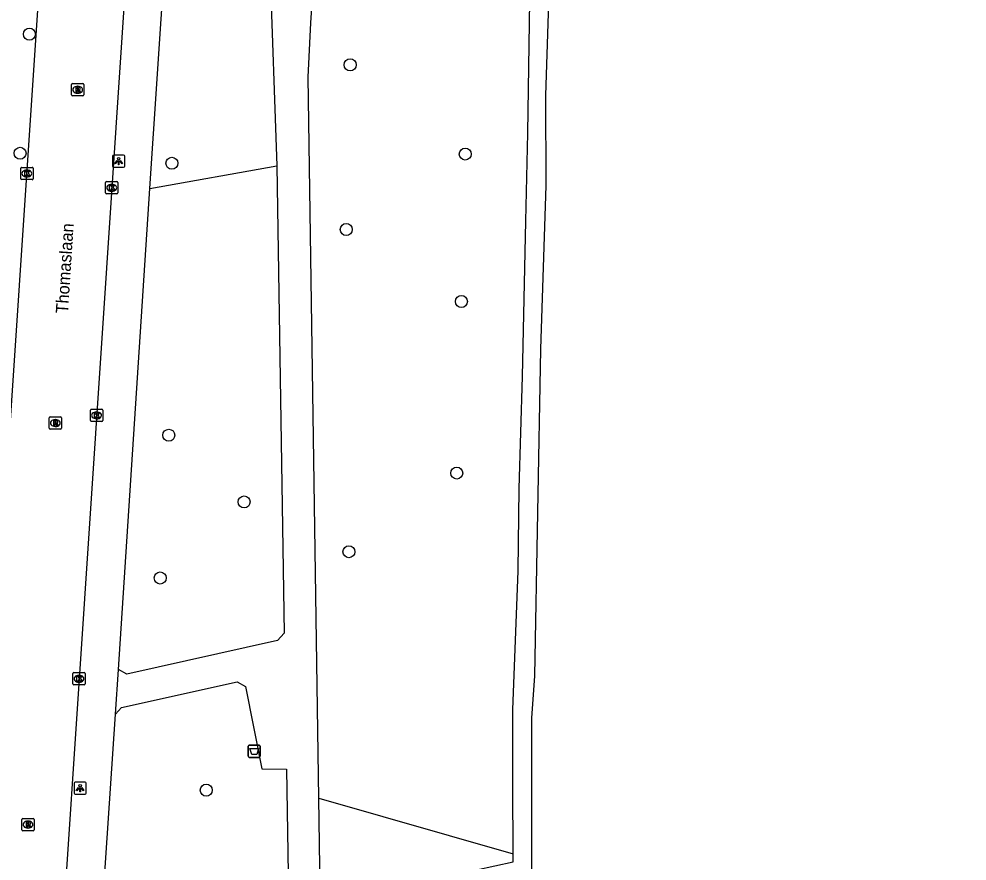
# Model space of a CAD drawing. Extents: x 161848 to 162726, y 385382 to 386521.
# Drawn here: x 162135.2 to 162212.3, y 385800.6 to 385869.2 of the extents above; entities that cross this region are included whole.
import ezdxf

# ---------------------------------------------------------------- set-up
doc = ezdxf.new("R2010")
doc.units = 0
for name, color, linetype in [('IMGEO_Afvalbak', 7, 'Continuous'), ('IMGEO_Boom', 7, 'Continuous'), ('IMGEO_Groenvoorziening', 7, 'Continuous'), ('IMGEO_Kolk', 7, 'Continuous'), ('IMGEO_Lichtpunt', 7, 'Continuous'), ('IMGEO_Openbare_ruimte_label', 7, 'Continuous'), ('IMGEO_Rijbaan_lokaal_open', 7, 'Continuous'), ('IMGEO_Rioolput', 7, 'Continuous'), ('IMGEO_Voetpad_halfverhard', 7, 'Continuous'), ('IMGEO_Voetpad_open', 7, 'Continuous'), ('IMGEO_Waterloop', 7, 'Continuous')]:
    doc.layers.add(name, color=color, linetype=linetype)

msp = doc.modelspace()

# ---------------------------------------------------------------- linework, layer by layer
at = {"layer": 'IMGEO_Afvalbak'}
for p, q in [((162153.805, 385809.196), (162153.805, 385809.996)), ((162153.805, 385809.996), (162153.805, 385809.196)), ((162153.905, 385810.096), (162154.695, 385810.096)), ((162154.695, 385810.096), (162153.905, 385810.096)), ((162154.795, 385809.996), (162154.795, 385809.196)), ((162154.795, 385809.196), (162154.795, 385809.996)), ((162154.695, 385809.096), (162153.905, 385809.096)), ((162153.905, 385809.096), (162154.695, 385809.096))]:
    msp.add_line(p, q, dxfattribs=at)
msp.add_lwpolyline([(162153.948, 385809.81), (162154.652, 385809.81), (162154.503, 385809.34), (162154.097, 385809.34), (162153.948, 385809.81)], dxfattribs=at)
for centre, start, end in [((162153.905, 385809.996), 90, 180), ((162153.905, 385809.996), 90, 180), ((162154.695, 385809.996), 0, 90), ((162154.695, 385809.996), 360, 90), ((162153.905, 385809.196), 180, 270), ((162153.905, 385809.196), 180, 270), ((162154.695, 385809.196), 270, 0), ((162154.695, 385809.196), 270, 0)]:
    msp.add_arc(centre, 0.1, start, end, dxfattribs=at)
at = {"layer": 'IMGEO_Boom'}
for centre in [(162136.001, 385867.99), (162162.116, 385865.497), (162135.242, 385858.291), (162171.483, 385858.232), (162147.602, 385857.479), (162161.796, 385852.085), (162171.166, 385846.218), (162147.348, 385835.331), (162170.786, 385832.247), (162153.48, 385829.892), (162162.014, 385825.84), (162146.654, 385823.702), (162150.402, 385806.424)]:
    msp.add_circle(centre, 0.489, dxfattribs=at)
at = {"layer": 'IMGEO_Groenvoorziening'}
for points in [[(162175.372, 385801.247), (162175.347, 385806.748), (162175.347, 385812.956), (162175.776, 385824.284), (162175.875, 385830.988), (162176.139, 385840.103), (162176.403, 385852.752), (162176.569, 385859.918), (162176.8, 385874.317)], [(162145.819, 385855.414), (162156.134, 385857.272)], [(162159.557, 385805.784), (162175.372, 385801.247)], [(162172.127, 385768.848), (162170.902, 385799.615), (162175.375, 385800.573), (162175.372, 385801.247)]]:
    msp.add_lwpolyline(points, dxfattribs=at)
at = {"layer": 'IMGEO_Kolk'}
for p, q in [((162135.3, 385856.217), (162135.3, 385857.069)), ((162135.375, 385857.143), (162136.227, 385857.143)), ((162135.788, 385856.923), (162135.813, 385856.923)), ((162136.301, 385857.069), (162136.301, 385856.217)), ((162136.227, 385856.143), (162135.375, 385856.143)), ((162135.811, 385856.363), (162135.786, 385856.363)), ((162142.206, 385855.061), (162142.206, 385855.913)), ((162142.281, 385855.987), (162143.133, 385855.987)), ((162142.694, 385855.767), (162142.719, 385855.767)), ((162143.207, 385855.913), (162143.207, 385855.061)), ((162142.717, 385855.207), (162142.692, 385855.207)), ((162143.133, 385854.987), (162142.281, 385854.987)), ((162140.971, 385836.522), (162140.971, 385837.374)), ((162141.046, 385837.448), (162141.898, 385837.448)), ((162141.972, 385837.374), (162141.972, 385836.522)), ((162141.482, 385836.668), (162141.457, 385836.668)), ((162141.459, 385837.228), (162141.484, 385837.228)), ((162141.898, 385836.448), (162141.046, 385836.448)), ((162139.544, 385815.071), (162139.544, 385815.923)), ((162139.619, 385815.997), (162140.471, 385815.997)), ((162140.032, 385815.777), (162140.057, 385815.777)), ((162140.545, 385815.923), (162140.545, 385815.071)), ((162140.471, 385814.997), (162139.619, 385814.997)), ((162140.055, 385815.217), (162140.03, 385815.217))]:
    msp.add_line(p, q, dxfattribs=at)
for points in [[(162135.3, 385856.217), (162135.3, 385857.069)], [(162135.375, 385857.143), (162136.227, 385857.143)], [(162135.621, 385856.843), (162135.744, 385856.843), (162135.744, 385856.692), (162135.874, 385856.843), (162136.038, 385856.843), (162135.892, 385856.692), (162136.045, 385856.443), (162135.893, 385856.443), (162135.808, 385856.607), (162135.744, 385856.54), (162135.744, 385856.443), (162135.621, 385856.443), (162135.621, 385856.843)], [(162136.301, 385857.069), (162136.301, 385856.217)], [(162136.227, 385856.143), (162135.375, 385856.143)], [(162142.206, 385855.061), (162142.206, 385855.913)], [(162142.281, 385855.987), (162143.133, 385855.987)], [(162143.207, 385855.913), (162143.207, 385855.061)], [(162142.527, 385855.687), (162142.65, 385855.687), (162142.65, 385855.536), (162142.78, 385855.687), (162142.944, 385855.687), (162142.798, 385855.536), (162142.951, 385855.287), (162142.799, 385855.287), (162142.714, 385855.451), (162142.65, 385855.384), (162142.65, 385855.287), (162142.527, 385855.287), (162142.527, 385855.687)], [(162143.133, 385854.987), (162142.281, 385854.987)], [(162140.971, 385836.522), (162140.971, 385837.374)], [(162141.046, 385837.448), (162141.898, 385837.448)], [(162141.972, 385837.374), (162141.972, 385836.522)], [(162141.292, 385837.148), (162141.415, 385837.148), (162141.415, 385836.997), (162141.545, 385837.148), (162141.709, 385837.148), (162141.563, 385836.997), (162141.716, 385836.748), (162141.564, 385836.748), (162141.479, 385836.912), (162141.415, 385836.845), (162141.415, 385836.748), (162141.292, 385836.748), (162141.292, 385837.148)], [(162141.898, 385836.448), (162141.046, 385836.448)], [(162139.544, 385815.071), (162139.544, 385815.923)], [(162139.619, 385815.997), (162140.471, 385815.997)], [(162139.865, 385815.697), (162139.988, 385815.697), (162139.988, 385815.546), (162140.118, 385815.697), (162140.282, 385815.697), (162140.136, 385815.546), (162140.289, 385815.297), (162140.137, 385815.297), (162140.052, 385815.461), (162139.988, 385815.394), (162139.988, 385815.297), (162139.865, 385815.297), (162139.865, 385815.697)], [(162140.545, 385815.923), (162140.545, 385815.071)], [(162140.471, 385814.997), (162139.619, 385814.997)]]:
    msp.add_lwpolyline(points, dxfattribs=at)
for centre, start, end in [((162135.377, 385857.067), 91.55205, 178.44795), ((162135.377, 385857.067), 91.55205, 178.44795), ((162136.225, 385857.067), 1.55205, 88.44795), ((162136.225, 385857.067), 1.55205, 88.44795), ((162135.377, 385856.219), 181.55205, 268.44795), ((162135.377, 385856.219), 181.55205, 268.44795), ((162136.225, 385856.219), 271.55205, 358.44795), ((162136.225, 385856.219), 271.55205, 358.44795), ((162142.283, 385855.911), 91.55205, 178.44795), ((162142.283, 385855.911), 91.55205, 178.44795), ((162143.131, 385855.911), 1.55205, 88.44795), ((162143.131, 385855.911), 1.55205, 88.44795), ((162142.283, 385855.063), 181.55205, 268.44795), ((162142.283, 385855.063), 181.55205, 268.44795), ((162143.131, 385855.063), 271.55205, 358.44795), ((162143.131, 385855.063), 271.55205, 358.44795), ((162141.048, 385837.372), 91.55205, 178.44795), ((162141.048, 385837.372), 91.55205, 178.44795), ((162141.896, 385837.372), 1.55205, 88.44795), ((162141.896, 385837.372), 1.55205, 88.44795), ((162141.048, 385836.524), 181.55205, 268.44795), ((162141.048, 385836.524), 181.55205, 268.44795), ((162141.896, 385836.524), 271.55205, 358.44795), ((162141.896, 385836.524), 271.55205, 358.44795), ((162139.621, 385815.921), 91.55205, 178.44795), ((162139.621, 385815.921), 91.55205, 178.44795), ((162140.469, 385815.921), 1.55205, 88.44795), ((162140.469, 385815.921), 1.55205, 88.44795), ((162139.621, 385815.073), 181.55205, 268.44795), ((162139.621, 385815.073), 181.55205, 268.44795), ((162140.469, 385815.073), 271.55205, 358.44795), ((162140.469, 385815.073), 271.55205, 358.44795)]:
    msp.add_arc(centre, 0.0765, start, end, dxfattribs=at)
for centre, major_axis, ratio, start_param, end_param in [((162135.787, 385856.643), (-0.387, 0.002), 0.722429, 4.712389, 7.853982), ((162135.812, 385856.643), (-0.39, 0.002), 0.717154, 1.570796, 4.712389), ((162142.693, 385855.487), (-0.387, 0.002), 0.722429, 4.712389, 7.853982), ((162142.718, 385855.487), (-0.39, 0.002), 0.717154, 1.570796, 4.712389), ((162141.458, 385836.948), (-0.387, 0.002), 0.722429, 4.712389, 7.853982), ((162141.483, 385836.948), (-0.39, 0.002), 0.717154, 1.570796, 4.712389), ((162140.031, 385815.497), (-0.387, 0.002), 0.722429, 4.712389, 7.853982), ((162140.056, 385815.497), (-0.39, 0.002), 0.717154, 1.570796, 4.712389)]:
    msp.add_ellipse(centre, major_axis=major_axis, ratio=ratio, start_param=start_param, end_param=end_param, dxfattribs=at)
at = {"layer": 'IMGEO_Lichtpunt'}
for p, q in [((162143.673, 385858.145), (162142.865, 385858.145)), ((162143.673, 385858.145), (162142.865, 385858.145)), ((162142.771, 385858.05), (162142.771, 385857.243)), ((162142.771, 385858.05), (162142.771, 385857.243)), ((162143.767, 385857.243), (162143.767, 385858.05)), ((162143.767, 385857.243), (162143.767, 385858.05)), ((162142.865, 385857.149), (162143.673, 385857.149)), ((162142.865, 385857.149), (162143.673, 385857.149)), ((162139.637, 385806.988), (162139.637, 385806.181)), ((162139.637, 385806.988), (162139.637, 385806.181)), ((162140.539, 385807.083), (162139.731, 385807.083)), ((162140.539, 385807.083), (162139.731, 385807.083)), ((162140.633, 385806.181), (162140.633, 385806.988)), ((162140.633, 385806.181), (162140.633, 385806.988)), ((162139.731, 385806.087), (162140.539, 385806.087)), ((162139.731, 385806.087), (162140.539, 385806.087))]:
    msp.add_line(p, q, dxfattribs=at)
for points in [[(162143.145, 385857.714), (162143.184, 385857.686), (162142.996, 385857.424), (162142.958, 385857.451), (162143.145, 385857.714)], [(162143.247, 385857.666), (162143.294, 385857.666), (162143.294, 385857.344), (162143.247, 385857.344), (162143.247, 385857.666)], [(162143.357, 385857.686), (162143.395, 385857.713), (162143.582, 385857.451), (162143.543, 385857.423), (162143.357, 385857.686)], [(162140.011, 385806.652), (162140.05, 385806.624), (162139.862, 385806.362), (162139.824, 385806.389), (162140.011, 385806.652)], [(162140.113, 385806.604), (162140.16, 385806.604), (162140.16, 385806.282), (162140.113, 385806.282), (162140.113, 385806.604)], [(162140.223, 385806.624), (162140.261, 385806.651), (162140.448, 385806.389), (162140.409, 385806.361), (162140.223, 385806.624)]]:
    msp.add_lwpolyline(points, dxfattribs=at)
for centre in [(162143.27, 385857.848), (162140.136, 385806.786)]:
    msp.add_circle(centre, 0.0994, dxfattribs=at)
for centre, start, end in [((162142.865, 385858.05), 90, 180), ((162142.865, 385858.05), 90, 180), ((162143.673, 385858.05), 0, 90), ((162143.673, 385858.05), 0, 90), ((162142.865, 385857.243), 180, 270), ((162142.865, 385857.243), 180, 270), ((162143.673, 385857.243), 270, 0), ((162143.673, 385857.243), 270, 360), ((162139.731, 385806.988), 90, 180), ((162139.731, 385806.988), 90, 180), ((162140.539, 385806.988), 0, 90), ((162140.539, 385806.988), 0, 90), ((162139.731, 385806.181), 180, 270), ((162139.731, 385806.181), 180, 270), ((162140.539, 385806.181), 270, 0), ((162140.539, 385806.181), 270, 360)]:
    msp.add_arc(centre, 0.0946, start, end, dxfattribs=at)
at = {"layer": 'IMGEO_Rijbaan_lokaal_open'}
for points in [[(162143.703, 385975.556), (162132.307, 385804.741)], [(162150.691, 385975.187), (162149.256, 385954.021), (162146.681, 385914.982), (162145.383, 385895.531), (162142.706, 385855.491), (162140.044, 385815.501), (162138.772, 385796.328), (162135.705, 385751.411)]]:
    msp.add_lwpolyline(points, dxfattribs=at)
at = {"layer": 'IMGEO_Rioolput'}
for p, q in [((162139.438, 385863.042), (162139.438, 385863.894)), ((162139.513, 385863.968), (162140.365, 385863.968)), ((162139.926, 385863.748), (162139.951, 385863.748)), ((162140.439, 385863.894), (162140.439, 385863.042)), ((162140.365, 385862.968), (162139.513, 385862.968)), ((162139.949, 385863.188), (162139.924, 385863.188)), ((162137.618, 385835.898), (162137.618, 385836.75)), ((162137.693, 385836.824), (162138.545, 385836.824)), ((162138.106, 385836.604), (162138.131, 385836.604)), ((162138.619, 385836.75), (162138.619, 385835.898)), ((162138.545, 385835.824), (162137.693, 385835.824)), ((162138.129, 385836.044), (162138.104, 385836.044)), ((162135.467, 385804.119), (162136.319, 385804.119)), ((162135.392, 385803.193), (162135.392, 385804.045)), ((162135.903, 385803.339), (162135.878, 385803.339)), ((162135.88, 385803.899), (162135.905, 385803.899)), ((162136.393, 385804.045), (162136.393, 385803.193)), ((162136.319, 385803.119), (162135.467, 385803.119))]:
    msp.add_line(p, q, dxfattribs=at)
for points in [[(162139.438, 385863.042), (162139.438, 385863.894)], [(162139.513, 385863.968), (162140.365, 385863.968)], [(162140.027, 385863.666), (162139.775, 385863.668), (162139.775, 385863.268)], [(162139.953, 385863.587), (162139.899, 385863.587), (162139.899, 385863.506)], [(162139.899, 385863.506), (162139.951, 385863.506)], [(162140.439, 385863.894), (162140.439, 385863.042)], [(162140.365, 385862.968), (162139.513, 385862.968)], [(162139.775, 385863.268), (162139.899, 385863.268), (162139.899, 385863.43), (162139.91, 385863.43)], [(162139.957, 385863.401), (162140.028, 385863.268), (162140.168, 385863.268), (162140.103, 385863.394)], [(162137.618, 385835.898), (162137.618, 385836.75)], [(162137.693, 385836.824), (162138.545, 385836.824)], [(162138.207, 385836.522), (162137.955, 385836.524), (162137.955, 385836.124)], [(162138.619, 385836.75), (162138.619, 385835.898)], [(162138.545, 385835.824), (162137.693, 385835.824)], [(162137.955, 385836.124), (162138.079, 385836.124), (162138.079, 385836.286), (162138.09, 385836.286)], [(162138.133, 385836.443), (162138.079, 385836.443), (162138.079, 385836.362)], [(162138.079, 385836.362), (162138.131, 385836.362)], [(162138.137, 385836.257), (162138.208, 385836.124), (162138.348, 385836.124), (162138.283, 385836.25)], [(162135.467, 385804.119), (162136.319, 385804.119)], [(162135.392, 385803.193), (162135.392, 385804.045)], [(162135.981, 385803.817), (162135.729, 385803.819), (162135.729, 385803.419)], [(162135.729, 385803.419), (162135.853, 385803.419), (162135.853, 385803.581), (162135.864, 385803.581)], [(162135.907, 385803.738), (162135.853, 385803.738), (162135.853, 385803.657)], [(162135.853, 385803.657), (162135.905, 385803.657)], [(162135.911, 385803.552), (162135.982, 385803.419), (162136.122, 385803.419), (162136.057, 385803.545)], [(162136.393, 385804.045), (162136.393, 385803.193)], [(162136.319, 385803.119), (162135.467, 385803.119)]]:
    msp.add_lwpolyline(points, dxfattribs=at)
for centre, radius, start, end in [((162139.515, 385863.892), 0.0765, 91.55205, 178.44795), ((162139.515, 385863.892), 0.0765, 91.55205, 178.44795), ((162139.935, 385863.695), 0.19, 274.7715, 282.96867), ((162139.959, 385863.491), 0.0964, 77.00612, 93.18647), ((162139.973, 385863.548), 0.0378, 276.66336, 79.67722), ((162140.026, 385863.556), 0.109, 350.36119, 89.41601), ((162140.024, 385863.556), 0.112, 277.58423, 350.98172), ((162140.363, 385863.892), 0.0765, 1.55205, 88.44795), ((162140.363, 385863.892), 0.0765, 1.55205, 88.44795), ((162139.515, 385863.044), 0.0765, 181.55205, 268.44795), ((162139.515, 385863.044), 0.0765, 181.55205, 268.44795), ((162139.909, 385863.377), 0.0533, 26.02933, 88.69889), ((162140.008, 385863.341), 0.108, 29.51342, 73.79051), ((162140.363, 385863.044), 0.0765, 271.55205, 358.44795), ((162140.363, 385863.044), 0.0765, 271.55205, 358.44795), ((162137.695, 385836.748), 0.0765, 91.55205, 178.44795), ((162137.695, 385836.748), 0.0765, 91.55205, 178.44795), ((162138.206, 385836.412), 0.109, 350.36119, 89.41601), ((162138.543, 385836.748), 0.0765, 1.55205, 88.44795), ((162138.543, 385836.748), 0.0765, 1.55205, 88.44795), ((162137.695, 385835.9), 0.0765, 181.55205, 268.44795), ((162137.695, 385835.9), 0.0765, 181.55205, 268.44795), ((162138.089, 385836.233), 0.0533, 26.02933, 88.69889), ((162138.115, 385836.551), 0.19, 274.7715, 282.96867), ((162138.139, 385836.347), 0.0964, 77.00612, 93.18647), ((162138.153, 385836.404), 0.0378, 276.66336, 79.67722), ((162138.204, 385836.412), 0.112, 277.58423, 350.98172), ((162138.188, 385836.197), 0.108, 29.51342, 73.79051), ((162138.543, 385835.9), 0.0765, 271.55205, 358.44795), ((162138.543, 385835.9), 0.0765, 271.55205, 358.44795), ((162135.469, 385804.043), 0.0765, 91.55205, 178.44795), ((162135.469, 385804.043), 0.0765, 91.55205, 178.44795), ((162136.317, 385804.043), 0.0765, 1.55205, 88.44795), ((162136.317, 385804.043), 0.0765, 1.55205, 88.44795), ((162135.863, 385803.528), 0.0533, 26.02933, 88.69889), ((162135.889, 385803.846), 0.19, 274.7715, 282.96867), ((162135.913, 385803.642), 0.0964, 77.00612, 93.18647), ((162135.927, 385803.699), 0.0378, 276.66336, 79.67722), ((162135.98, 385803.707), 0.109, 350.36119, 89.41601), ((162135.978, 385803.707), 0.112, 277.58423, 350.98172), ((162135.962, 385803.492), 0.108, 29.51342, 73.79051), ((162135.469, 385803.195), 0.0765, 181.55205, 268.44795), ((162135.469, 385803.195), 0.0765, 181.55205, 268.44795), ((162136.317, 385803.195), 0.0765, 271.55205, 358.44795), ((162136.317, 385803.195), 0.0765, 271.55205, 358.44795)]:
    msp.add_arc(centre, radius, start, end, dxfattribs=at)
for centre, major_axis, ratio, start_param, end_param in [((162139.925, 385863.468), (-0.387, 0.002), 0.722429, 4.712389, 7.853982), ((162139.95, 385863.468), (-0.39, 0.002), 0.717154, 1.570796, 4.712389), ((162138.105, 385836.324), (-0.387, 0.002), 0.722429, 4.712389, 7.853982), ((162138.13, 385836.324), (-0.39, 0.002), 0.717154, 1.570796, 4.712389), ((162135.879, 385803.619), (-0.387, 0.002), 0.722429, 4.712389, 7.853982), ((162135.904, 385803.619), (-0.39, 0.002), 0.717154, 1.570796, 4.712389)]:
    msp.add_ellipse(centre, major_axis=major_axis, ratio=ratio, start_param=start_param, end_param=end_param, dxfattribs=at)
at = {"layer": 'IMGEO_Voetpad_halfverhard'}
for points in [[(162159.557, 385805.784), (162158.695, 385864.488), (162158.9, 385868.909), (162163.127, 385930.755), (162166.494, 385941.466), (162166.953, 385942.268), (162191.432, 385969.273), (162195.081, 385973.92), (162195.654, 385975.073), (162196.057, 385976.295), (162202.458, 386000), (162212.322, 386037.98)], [(162155.575, 385873.467), (162156.134, 385857.272)], [(162156.134, 385857.272), (162156.736, 385819.213), (162156.209, 385818.61), (162143.943, 385815.882), (162143.259, 385816.251)], [(162143.016, 385812.624), (162143.498, 385813.15), (162152.92, 385815.252), (162153.602, 385814.866), (162154.917, 385808.163), (162156.935, 385808.144), (162157.103, 385797.911)], [(162160.103, 385768.548), (162159.557, 385805.784)]]:
    msp.add_lwpolyline(points, dxfattribs=at)
at = {"layer": 'IMGEO_Voetpad_open'}
for points in [[(162145.819, 385855.414), (162147.017, 385873.732)], [(162143.259, 385816.251), (162145.819, 385855.414)], [(162143.016, 385812.624), (162143.259, 385816.251)], [(162141.848, 385795.27), (162143.016, 385812.624)]]:
    msp.add_lwpolyline(points, dxfattribs=at)
at = {"layer": 'IMGEO_Waterloop'}
msp.add_lwpolyline([(162182.725, 385943.542), (162182.102, 385935.109), (162180.602, 385920.392), (162179.262, 385894.577), (162178.816, 385888.175), (162178.001, 385862.984), (162178.03, 385855.675), (162177.6, 385842.344), (162177.129, 385815.735), (162176.868, 385812.284), (162176.867, 385800.819), (162176.867, 385800.784), (162176.862, 385760.126), (162176.657, 385753.475), (162176.783, 385750), (162176.854, 385748.052)], dxfattribs=at)

# ---------------------------------------------------------------- texts
at = {"layer": 'IMGEO_Openbare_ruimte_label'}
msp.add_text('Thomaslaan', height=1, rotation=86.33075, dxfattribs=at).set_placement((162139.141, 385845.216))

doc.saveas('drawing.dxf')
